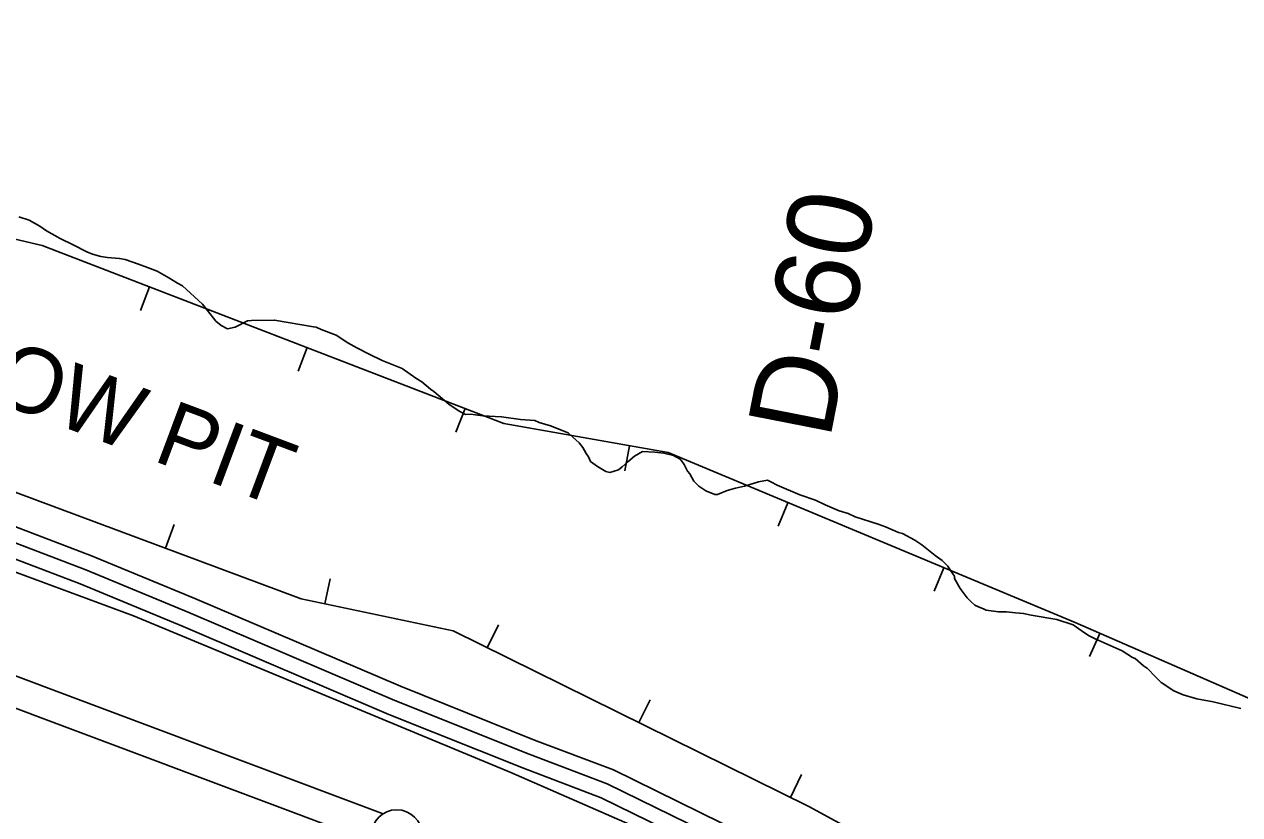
# Model space of a CAD drawing. Extents: x 3279314 to 3317160, y 734079 to 759431.
# Drawn here: x 3289202 to 3290400, y 751596 to 752375 of the extents above; entities that cross this region are included whole.
import ezdxf

# ---------------------------------------------------------------- set-up
doc = ezdxf.new("R2010")
doc.units = 0
for name, color, linetype in [('V-BORW-IDEN', 7, 'Continuous'), ('V-BORW-LINE', 7, 'Continuous'), ('V-LEVE-TOET', 7, 'Continuous'), ('V-RIVR-RANG-IDEN', 7, 'Continuous'), ('V-ROAD-CNTR', 7, 'Continuous'), ('V-SITE-VEGE', 7, 'Continuous'), ('V-SURV-LINE', 7, 'Continuous')]:
    doc.layers.add(name, color=color, linetype=linetype)

msp = doc.modelspace()

# ---------------------------------------------------------------- linework, layer by layer
at = {"layer": 'V-BORW-LINE'}
for p, q in [((3289325.3, 752116.5), (3289316.3, 752093.1)), ((3289480.8, 752056.5), (3289471.8, 752033.2)), ((3289636.2, 751996.6), (3289627.2, 751973.3)), ((3289798.2, 751959.9), (3289793.8, 751935.3)), ((3289954.3, 751903.8), (3289944.6, 751880.8)), ((3289341, 751859), (3289349.7, 751882.4)), ((3290108, 751839.6), (3290098.4, 751816.5)), ((3289498.1, 751804.2), (3289503.3, 751828.7)), ((3289658, 751760.8), (3289669.1, 751783.3)), ((3290261.6, 751775), (3290251.6, 751752.1)), ((3289807.5, 751687.2), (3289818.5, 751709.6)), ((3289956.9, 751613.5), (3289967.9, 751636))]:
    msp.add_line(p, q, dxfattribs=at)
for points in [[(3287842.3, 752588.2), (3288177.4, 752462.4), (3288402.9, 752400.4), (3288618.4, 752337.5), (3288751.8, 752316.1), (3288970.3, 752257.8), (3289060.5, 752199.2), (3289159, 752171.1), (3289219.5, 752157.3), (3289674.3, 751981.9), (3289836.5, 751953.1), (3290237.3, 751785.6), (3290641.7, 751609.4), (3291148.6, 751375)], [(3291148.6, 751375), (3290641.7, 751609.4), (3290237.3, 751785.6), (3289836.5, 751953.1), (3289674.3, 751981.9), (3289219.5, 752157.3), (3289159, 752171.1), (3289060.5, 752199.2), (3288970.3, 752257.8), (3288751.8, 752316.1), (3288618.4, 752337.5), (3288402.9, 752400.4), (3288177.4, 752462.4), (3287842.3, 752588.2)], [(3292476.4, 750599.1), (3292188.6, 750640), (3291942.7, 750724.6), (3291713.9, 750817.6), (3291454.1, 750951.1), (3291413.2, 750974.1), (3291247.6, 751022.2), (3290989.6, 751144.6), (3290648.7, 751279.3), (3290212.2, 751475.5), (3289975.1, 751604.5), (3289624.4, 751777.4), (3289474.8, 751809.2), (3289073.7, 751958.5), (3288634.1, 752099.5), (3288076.2, 752324.8), (3287513.5, 752526.9)], [(3287513.5, 752526.9), (3288076.2, 752324.8), (3288634.1, 752099.5), (3289073.7, 751958.5), (3289474.8, 751809.2), (3289624.4, 751777.4), (3289975.1, 751604.5), (3290212.2, 751475.5), (3290648.7, 751279.3), (3290989.6, 751144.6), (3291247.6, 751022.2), (3291413.2, 750974.1), (3291454.1, 750951.1), (3291713.9, 750817.6), (3291942.7, 750724.6), (3292188.6, 750640), (3292476.4, 750599.1)]]:
    msp.add_lwpolyline(points, dxfattribs=at)
at = {"layer": 'V-LEVE-TOET'}
msp.add_lwpolyline([(3291978.2, 750613.6), (3291945.9, 750627.3), (3291840.3, 750672.2), (3291730.1, 750720.4), (3291692.3, 750737.9), (3291590.5, 750778.4), (3291498.8, 750821.8), (3291451.5, 750843.7), (3291366.4, 750882.6), (3291320.2, 750909), (3291256.7, 750937), (3290935.8, 751073.4), (3290635.4, 751213.7), (3290337.3, 751346.9), (3290015.2, 751492.2), (3289681.5, 751638), (3289309.5, 751792.4), (3288910.2, 751940), (3288557.3, 752056.2), (3288101.3, 752234.1), (3287745, 752353.6)], dxfattribs=at)
at = {"layer": 'V-ROAD-CNTR'}
for points in [[(3289909.8, 751578), (3289782.4, 751640.6), (3289704.7, 751670), (3289572.7, 751722.9), (3289370, 751809.3), (3289268.1, 751851.5), (3289132.2, 751903.3), (3288906.3, 751977), (3288841.4, 752005.3), (3288766.9, 752035.4), (3288685.1, 752059.3), (3288436.7, 752152), (3288347.1, 752177.2), (3288094.7, 752274.8), (3287981.3, 752322.7), (3287938.2, 752332.4), (3287908.7, 752330.8), (3287885, 752337.2), (3287846.6, 752347.5)], [(3289903.1, 751564.6), (3289776.4, 751626.8), (3289699.3, 751656.1), (3289567, 751709), (3289364.2, 751795.5), (3289262.6, 751837.6), (3289127.2, 751889.2), (3288901, 751963), (3288835.6, 751991.5), (3288762, 752021.2), (3288680.3, 752045.1), (3288432.1, 752137.7), (3288342.4, 752162.9), (3288089.1, 752260.9), (3287976.7, 752308.3), (3287936.9, 752317.3), (3287907.1, 752315.6), (3287881.1, 752322.7), (3287841.2, 752333.4)], [(3289903.1, 751564.6), (3289776.4, 751626.8), (3289699.3, 751656.1), (3289567, 751709), (3289364.2, 751795.5), (3289262.6, 751837.6), (3289127.2, 751889.2), (3288901, 751963), (3288835.6, 751991.5), (3288762, 752021.2), (3288680.3, 752045.1), (3288432.1, 752137.7), (3288342.4, 752162.9), (3288089.1, 752260.9), (3287976.7, 752308.3), (3287936.9, 752317.3), (3287907.1, 752315.6), (3287881.1, 752322.7), (3287841.2, 752333.4)], [(3289896.4, 751551.2), (3289770.4, 751613), (3289693.8, 751642.1), (3289561.2, 751695.2), (3289358.4, 751781.7), (3289257, 751823.7), (3289122.2, 751875), (3288895.7, 751948.9), (3288829.8, 751977.6), (3288757.1, 752007), (3288675.6, 752030.8), (3288427.4, 752123.4), (3288337.6, 752148.7), (3288083.5, 752247), (3287972.1, 752294), (3287935.6, 752302.2), (3287905.5, 752300.5), (3287877.2, 752308.3), (3287835.9, 752319.3)]]:
    msp.add_lwpolyline(points, dxfattribs=at)
at = {"layer": 'V-SITE-VEGE'}
for points in [[(3289332.9, 752131.8), (3289323.4, 752135.6), (3289314.5, 752138.9), (3289301.2, 752143.2), (3289295.6, 752144.3), (3289284, 752145.4), (3289277.3, 752146.4), (3289269, 752148.6), (3289263.4, 752150.8), (3289250, 752157.9), (3289237.2, 752164), (3289223.9, 752171.7), (3289217.2, 752176.1), (3289206.6, 752182.1), (3289196.6, 752185.4)], [(3290186.4, 751794.7), (3290178.7, 751795.2), (3290169.8, 751796.2), (3290162, 751796.2), (3290149.8, 751797.8), (3290147.6, 751798.9), (3290142, 751801.1), (3290138.7, 751802.7), (3290134.8, 751806), (3290130.9, 751809.9), (3290124.2, 751819.3), (3290118.6, 751829.2), (3290118.5, 751831.5), (3290114.6, 751837), (3290111.8, 751841.4), (3290106.2, 751846.9), (3290099.6, 751851.9), (3290086.2, 751862.4), (3290079.5, 751866.8), (3290067.3, 751873.4), (3290063.4, 751874.4), (3290050.6, 751879.9), (3290043.4, 751882.7), (3290020.6, 751889.7), (3290013.9, 751893), (3290005, 751895.8), (3289991.1, 751901.8), (3289981.6, 751906.2), (3289966.1, 751911.6), (3289943.8, 751921), (3289937.7, 751924.2), (3289934.4, 751925.9), (3289925.5, 751924.2), (3289911.6, 751920.2), (3289902.8, 751918), (3289894.5, 751915.7), (3289885.1, 751911.8), (3289882.3, 751911.7), (3289873.4, 751915.6), (3289866.7, 751920), (3289861.7, 751924.9), (3289857.8, 751932.1), (3289855.5, 751934.9), (3289852.2, 751941.5), (3289849.9, 751944.8), (3289848.2, 751946.5), (3289841.6, 751950.4), (3289832.1, 751952.5), (3289823.2, 751953.6), (3289811, 751954.1), (3289803.3, 751949.6), (3289796.7, 751944), (3289791.1, 751939), (3289787.3, 751936.2), (3289779, 751933.4), (3289775.1, 751934.4), (3289766.7, 751939.4), (3289760, 751944.4), (3289757.8, 751948.8), (3289755.5, 751952.1), (3289752.2, 751958.2), (3289748.8, 751962.6), (3289742.1, 751968.7), (3289737.7, 751972.5), (3289720.4, 751979.6), (3289709.3, 751982.9), (3289704.9, 751984.6), (3289691, 751985.6), (3289672.1, 751988.3), (3289653.8, 751989.3), (3289646.6, 751990.3), (3289641.6, 751990.9), (3289636.6, 751990.8), (3289630.5, 751994.1), (3289620.4, 752000.7), (3289605.4, 752013.4), (3289602.1, 752015.6), (3289593.7, 752022.8), (3289587.6, 752026.6), (3289574.2, 752036), (3289554.7, 752043.7), (3289541.9, 752050.2), (3289529.7, 752056.3), (3289520.8, 752061.2), (3289509.1, 752068.9), (3289494.6, 752074.4), (3289489.6, 752076.6), (3289486.9, 752077.1), (3289448.5, 752083.6), (3289425.8, 752083.4), (3289421.9, 752082.9), (3289409.7, 752076.7), (3289402, 752075), (3289395.9, 752078.3), (3289390.8, 752082.7), (3289382.5, 752093.2), (3289377.4, 752099.3), (3289357.9, 752117.5), (3289352.9, 752120.2), (3289344.5, 752125.2), (3289332.9, 752131.8)], [(3290400.6, 751701), (3290373.4, 751707.5), (3290357.2, 751710.7), (3290343.9, 751714.5), (3290334.5, 751718.4), (3290322.2, 751726.6), (3290316.1, 751732.7), (3290308.8, 751740.4), (3290304.9, 751743.2), (3290296.5, 751750.3), (3290293.8, 751751.4), (3290283.7, 751758), (3290257, 751769.5), (3290250.4, 751772.8), (3290244.2, 751777.2), (3290235.3, 751783.3), (3290219.2, 751788.7), (3290194.2, 751793), (3290186.4, 751794.7)]]:
    msp.add_lwpolyline(points, dxfattribs=at)
at = {"layer": 'V-SURV-LINE'}
for points in [[(3288749.3, 751899.7), (3289555.5, 751597.3)], [(3289544.9, 751569.2), (3288738.8, 751871.7)]]:
    msp.add_lwpolyline(points, dxfattribs=at)
msp.add_circle((3289568.9, 751576.3), 25, dxfattribs=at)

# ---------------------------------------------------------------- texts
at = {"layer": 'V-BORW-IDEN'}
msp.add_text('BORROW PIT', height=64, rotation=339.4636, dxfattribs=at).set_placement((3288935.4, 752092.5))
at = {"layer": 'V-RIVR-RANG-IDEN'}
msp.add_text('D-60', height=83, rotation=78.8953, dxfattribs=at).set_placement((3289995.6, 751964.9))

doc.saveas('drawing.dxf')
